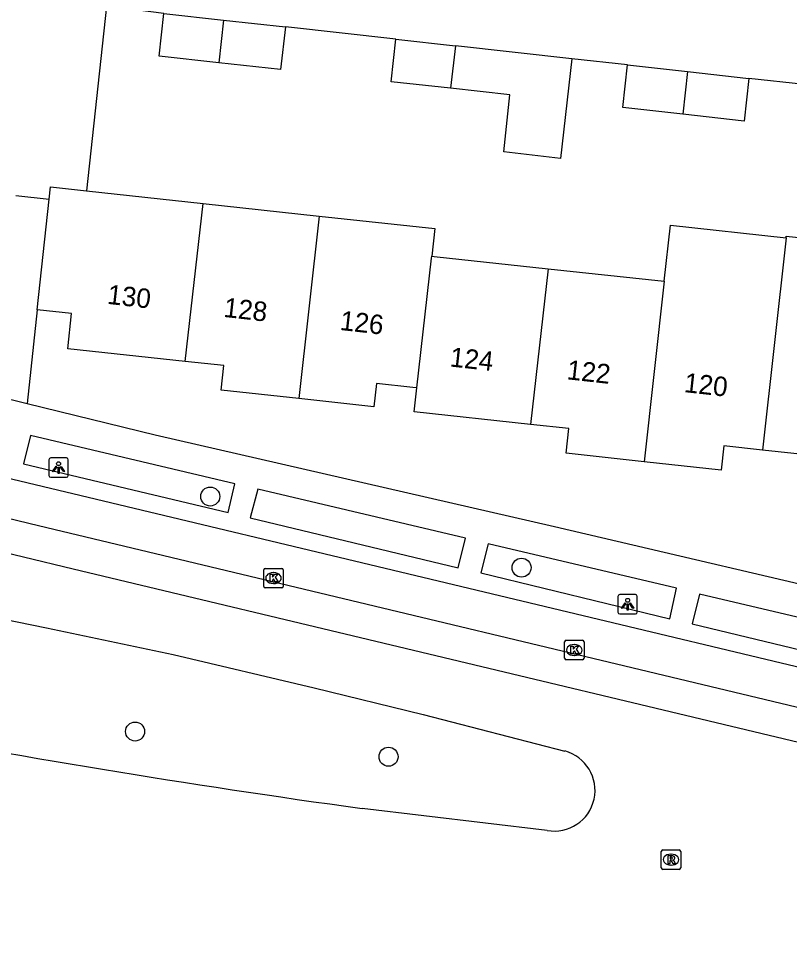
# Model space of a CAD drawing. Extents: x 162026 to 163499, y 387297 to 388169.
# Drawn here: x 162397.42 to 162437.09, y 387380.41 to 387428.11 of the extents above; entities that cross this region are included whole.
import ezdxf

# ---------------------------------------------------------------- set-up
doc = ezdxf.new("R2010")
doc.units = 0
for name, color, linetype in [('IMGEO_Boom', 7, 'Continuous'), ('IMGEO_Kolk', 7, 'Continuous'), ('IMGEO_Lichtpunt', 7, 'Continuous'), ('IMGEO_Pand', 7, 'Continuous'), ('IMGEO_Pand_nummerreeks', 7, 'Continuous'), ('IMGEO_Rijbaan_lokaal_gesloten', 7, 'Continuous'), ('IMGEO_Rijbaan_lokaal_open', 7, 'Continuous'), ('IMGEO_Rioolput', 7, 'Continuous'), ('IMGEO_Voetpad_open', 7, 'Continuous')]:
    doc.layers.add(name, color=color, linetype=linetype)

msp = doc.modelspace()

# ---------------------------------------------------------------- linework, layer by layer
at = {"layer": 'IMGEO_Boom'}
for centre in [(162407.286, 387403.51), (162423.306, 387399.849), (162403.416, 387391.416), (162416.459, 387390.119)]:
    msp.add_circle(centre, 0.489, dxfattribs=at)
at = {"layer": 'IMGEO_Kolk'}
for p, q in [((162410.039, 387398.886), (162410.039, 387399.738)), ((162410.114, 387399.812), (162410.966, 387399.812)), ((162411.04, 387399.738), (162411.04, 387398.886)), ((162410.527, 387399.592), (162410.552, 387399.592)), ((162410.966, 387398.812), (162410.114, 387398.812)), ((162410.55, 387399.032), (162410.525, 387399.032)), ((162425.52, 387395.183), (162425.52, 387396.035)), ((162425.595, 387396.109), (162426.447, 387396.109)), ((162426.008, 387395.889), (162426.033, 387395.889)), ((162426.521, 387396.035), (162426.521, 387395.183)), ((162426.447, 387395.109), (162425.595, 387395.109)), ((162426.031, 387395.329), (162426.006, 387395.329))]:
    msp.add_line(p, q, dxfattribs=at)
for points in [[(162410.039, 387398.886), (162410.039, 387399.738)], [(162410.114, 387399.812), (162410.966, 387399.812)], [(162411.04, 387399.738), (162411.04, 387398.886)], [(162410.36, 387399.512), (162410.483, 387399.512), (162410.483, 387399.361), (162410.613, 387399.512), (162410.777, 387399.512), (162410.631, 387399.361), (162410.784, 387399.112), (162410.632, 387399.112), (162410.547, 387399.276), (162410.483, 387399.209), (162410.483, 387399.112), (162410.36, 387399.112), (162410.36, 387399.512)], [(162410.966, 387398.812), (162410.114, 387398.812)], [(162425.52, 387395.183), (162425.52, 387396.035)], [(162425.595, 387396.109), (162426.447, 387396.109)], [(162426.521, 387396.035), (162426.521, 387395.183)], [(162425.841, 387395.809), (162425.964, 387395.809), (162425.964, 387395.658), (162426.094, 387395.809), (162426.258, 387395.809), (162426.112, 387395.658), (162426.265, 387395.409), (162426.113, 387395.409), (162426.028, 387395.573), (162425.964, 387395.506), (162425.964, 387395.409), (162425.841, 387395.409), (162425.841, 387395.809)], [(162426.447, 387395.109), (162425.595, 387395.109)]]:
    msp.add_lwpolyline(points, dxfattribs=at)
for centre, start, end in [((162410.116, 387399.736), 91.552, 178.448), ((162410.116, 387399.736), 91.552, 178.448), ((162410.964, 387399.736), 1.552, 88.448), ((162410.964, 387399.736), 1.552, 88.448), ((162410.116, 387398.888), 181.552, 268.448), ((162410.116, 387398.888), 181.552, 268.448), ((162410.964, 387398.888), 271.552, 358.448), ((162410.964, 387398.888), 271.552, 358.448), ((162425.597, 387396.033), 91.552, 178.448), ((162425.597, 387396.033), 91.552, 178.448), ((162426.445, 387396.033), 1.552, 88.448), ((162426.445, 387396.033), 1.552, 88.448), ((162425.597, 387395.185), 181.552, 268.448), ((162425.597, 387395.185), 181.552, 268.448), ((162426.445, 387395.185), 271.552, 358.448), ((162426.445, 387395.185), 271.552, 358.448)]:
    msp.add_arc(centre, 0.0765, start, end, dxfattribs=at)
for centre, major_axis, ratio, start_param, end_param in [((162410.526, 387399.312), (-0.387, 0.002), 0.722429, 4.712389, 7.853982), ((162410.551, 387399.312), (-0.39, 0.002), 0.717154, 1.570796, 4.712389), ((162426.007, 387395.609), (-0.387, 0.002), 0.722429, 4.712389, 7.853982), ((162426.032, 387395.609), (-0.39, 0.002), 0.717154, 1.570796, 4.712389)]:
    msp.add_ellipse(centre, major_axis=major_axis, ratio=ratio, start_param=start_param, end_param=end_param, dxfattribs=at)
at = {"layer": 'IMGEO_Lichtpunt'}
for p, q in [((162398.98, 387405.4), (162398.98, 387404.593)), ((162398.98, 387405.4), (162398.98, 387404.593)), ((162399.882, 387405.495), (162399.074, 387405.495)), ((162399.882, 387405.495), (162399.074, 387405.495)), ((162399.976, 387404.593), (162399.976, 387405.4)), ((162399.976, 387404.593), (162399.976, 387405.4)), ((162399.074, 387404.499), (162399.882, 387404.499)), ((162399.074, 387404.499), (162399.882, 387404.499)), ((162428.267, 387398.371), (162428.267, 387397.564)), ((162428.267, 387398.371), (162428.267, 387397.564)), ((162429.169, 387398.466), (162428.361, 387398.466)), ((162429.169, 387398.466), (162428.361, 387398.466)), ((162429.263, 387397.564), (162429.263, 387398.371)), ((162429.263, 387397.564), (162429.263, 387398.371)), ((162428.361, 387397.47), (162429.169, 387397.47)), ((162428.361, 387397.47), (162429.169, 387397.47))]:
    msp.add_line(p, q, dxfattribs=at)
for points in [[(162399.354, 387405.064), (162399.393, 387405.036), (162399.205, 387404.774), (162399.167, 387404.801), (162399.354, 387405.064)], [(162399.456, 387405.016), (162399.503, 387405.016), (162399.503, 387404.694), (162399.456, 387404.694), (162399.456, 387405.016)], [(162399.566, 387405.036), (162399.604, 387405.063), (162399.791, 387404.801), (162399.752, 387404.773), (162399.566, 387405.036)], [(162428.641, 387398.035), (162428.68, 387398.007), (162428.492, 387397.745), (162428.454, 387397.772), (162428.641, 387398.035)], [(162428.743, 387397.987), (162428.79, 387397.987), (162428.79, 387397.665), (162428.743, 387397.665), (162428.743, 387397.987)], [(162428.853, 387398.007), (162428.891, 387398.034), (162429.078, 387397.772), (162429.039, 387397.744), (162428.853, 387398.007)]]:
    msp.add_lwpolyline(points, dxfattribs=at)
for centre in [(162399.479, 387405.198), (162428.766, 387398.169)]:
    msp.add_circle(centre, 0.0994, dxfattribs=at)
for centre, start, end in [((162399.074, 387405.4), 90, 180), ((162399.074, 387405.4), 90, 180), ((162399.882, 387405.4), 0, 90), ((162399.882, 387405.4), 0, 90), ((162399.074, 387404.593), 180, 270), ((162399.074, 387404.593), 180, 270), ((162399.882, 387404.593), 270, 0), ((162399.882, 387404.593), 270, 360), ((162428.361, 387398.371), 90, 180), ((162428.361, 387398.371), 90, 180), ((162429.169, 387398.371), 0, 90), ((162429.169, 387398.371), 0, 90), ((162428.361, 387397.564), 180, 270), ((162428.361, 387397.564), 180, 270), ((162429.169, 387397.564), 270, 0), ((162429.169, 387397.564), 270, 360)]:
    msp.add_arc(centre, 0.0946, start, end, dxfattribs=at)
at = {"layer": 'IMGEO_Pand'}
for points in [[(162407.724, 387425.836), (162404.65, 387426.18), (162404.89, 387428.37)], [(162404.89, 387428.37), (162407.97, 387428.03)], [(162407.97, 387428.03), (162407.724, 387425.836)], [(162407.97, 387428.03), (162411.15, 387427.68)], [(162411.15, 387427.68), (162410.9, 387425.48), (162407.724, 387425.836)], [(162419.657, 387424.518), (162416.6, 387424.86), (162416.84, 387427.05)], [(162416.84, 387427.05), (162419.904, 387426.712)], [(162419.904, 387426.712), (162419.657, 387424.518)], [(162425.89, 387426.044), (162419.904, 387426.712)], [(162425.89, 387426.044), (162425.318, 387420.914), (162422.396, 387421.242), (162422.709, 387424.176), (162419.657, 387424.518)], [(162431.598, 387423.184), (162428.51, 387423.53), (162428.75, 387425.72)], [(162428.75, 387425.72), (162431.842, 387425.379)], [(162431.842, 387425.379), (162431.598, 387423.184)], [(162435.01, 387425.03), (162434.76, 387422.83), (162431.598, 387423.184)], [(162431.842, 387425.379), (162435.01, 387425.03)], [(162398.996, 387418.812), (162399.064, 387419.442), (162400.911, 387419.241)], [(162400.911, 387419.241), (162406.912, 387418.59)], [(162398.38, 387413.12), (162398.996, 387418.812)], [(162406.001, 387410.462), (162406.912, 387418.59)], [(162406.912, 387418.59), (162412.884, 387417.942)], [(162412.884, 387417.942), (162411.84, 387408.552)], [(162412.884, 387417.942), (162418.844, 387417.296), (162418.685, 387415.884)], [(162430.645, 387414.587), (162430.965, 387417.474), (162436.918, 387416.828)], [(162436.918, 387416.828), (162436.927, 387416.912), (162442.872, 387416.267), (162442.549, 387413.295), (162441.676, 387405.253), (162435.704, 387405.901)], [(162436.918, 387416.828), (162435.704, 387405.901)], [(162417.922, 387409.102), (162418.674, 387415.784), (162418.685, 387415.884)], [(162418.685, 387415.884), (162418.808, 387415.871), (162424.683, 387415.234)], [(162424.683, 387415.234), (162423.767, 387407.219)], [(162424.683, 387415.234), (162430.645, 387414.587)], [(162430.645, 387414.587), (162429.615, 387405.3)], [(162406.001, 387410.462), (162399.952, 387411.118), (162400.149, 387412.928), (162398.38, 387413.12)], [(162411.84, 387408.552), (162407.851, 387408.985), (162407.988, 387410.246), (162406.001, 387410.462)], [(162417.922, 387409.102), (162417.71, 387409.125), (162415.833, 387409.328), (162415.703, 387408.133), (162411.84, 387408.552)], [(162423.767, 387407.219), (162417.783, 387407.869), (162417.922, 387409.102)], [(162429.615, 387405.3), (162425.601, 387405.735), (162425.739, 387407.005), (162423.767, 387407.219)], [(162435.704, 387405.901), (162433.715, 387406.117), (162433.58, 387404.87), (162429.615, 387405.3)]]:
    msp.add_lwpolyline(points, dxfattribs=at)
at = {"layer": 'IMGEO_Rijbaan_lokaal_gesloten'}
for points in [[(162481.027, 387380.405), (162452.771, 387387.216), (162400.227, 387399.776), (162389.995, 387402.241), (162380.574, 387405.433)], [(162443.887, 387391.121), (162398.449, 387402.001), (162390.78, 387403.852), (162390.534, 387403.927)]]:
    msp.add_lwpolyline(points, dxfattribs=at)
at = {"layer": 'IMGEO_Rijbaan_lokaal_open'}
for points in [[(162404.89, 387428.37), (162401.939, 387428.743), (162400.911, 387419.241)], [(162416.84, 387427.05), (162411.15, 387427.68)], [(162428.75, 387425.72), (162425.89, 387426.044)], [(162437.861, 387424.709), (162435.01, 387425.03)], [(162397.281, 387418.997), (162398.996, 387418.812)], [(162376.494, 387401.259), (162376.793, 387401.271), (162398.853, 387396.753), (162405.374, 387395.373), (162412.634, 387393.669), (162418.248, 387392.291), (162425.53, 387390.413)], [(162424.617, 387386.324), (162415.106, 387387.454)]]:
    msp.add_lwpolyline(points, dxfattribs=at)
for centre, radius, start, end in [((162482.945, 387881.492), 498.674, 259.07678, 262.18127), ((162424.991, 387388.387), 2.097, 259.7128, 75.1139)]:
    msp.add_arc(centre, radius, start, end, dxfattribs=at)
at = {"layer": 'IMGEO_Rioolput'}
for p, q in [((162430.494, 387384.396), (162430.494, 387385.248)), ((162430.569, 387385.322), (162431.421, 387385.322)), ((162430.982, 387385.102), (162431.007, 387385.102)), ((162431.495, 387385.248), (162431.495, 387384.396)), ((162431.005, 387384.542), (162430.98, 387384.542)), ((162431.421, 387384.322), (162430.569, 387384.322))]:
    msp.add_line(p, q, dxfattribs=at)
for points in [[(162430.494, 387384.396), (162430.494, 387385.248)], [(162430.569, 387385.322), (162431.421, 387385.322)], [(162431.083, 387385.02), (162430.831, 387385.022), (162430.831, 387384.622)], [(162431.009, 387384.941), (162430.955, 387384.941), (162430.955, 387384.86)], [(162431.495, 387385.248), (162431.495, 387384.396)], [(162430.831, 387384.622), (162430.955, 387384.622), (162430.955, 387384.784), (162430.966, 387384.784)], [(162430.955, 387384.86), (162431.007, 387384.86)], [(162431.013, 387384.755), (162431.084, 387384.622), (162431.224, 387384.622), (162431.159, 387384.748)], [(162431.421, 387384.322), (162430.569, 387384.322)]]:
    msp.add_lwpolyline(points, dxfattribs=at)
for centre, radius, start, end in [((162430.571, 387385.246), 0.0765, 91.552, 178.448), ((162430.571, 387385.246), 0.0765, 91.552, 178.448), ((162431.015, 387384.845), 0.0964, 77.0061, 93.1865), ((162431.029, 387384.902), 0.0378, 276.6634, 79.6772), ((162431.082, 387384.91), 0.109, 350.3612, 89.416), ((162431.08, 387384.91), 0.112, 277.5842, 350.9817), ((162431.419, 387385.246), 0.0765, 1.552, 88.448), ((162431.419, 387385.246), 0.0765, 1.552, 88.448), ((162430.571, 387384.398), 0.0765, 181.552, 268.448), ((162430.571, 387384.398), 0.0765, 181.552, 268.448), ((162430.965, 387384.731), 0.0533, 26.0293, 88.6989), ((162430.991, 387385.049), 0.19, 274.7715, 282.9687), ((162431.064, 387384.695), 0.108, 29.5134, 73.7905), ((162431.419, 387384.398), 0.0765, 271.552, 358.448), ((162431.419, 387384.398), 0.0765, 271.552, 358.448)]:
    msp.add_arc(centre, radius, start, end, dxfattribs=at)
for centre, major_axis, ratio, start_param, end_param in [((162430.981, 387384.822), (-0.387, 0.002), 0.722429, 4.712389, 7.853982), ((162431.006, 387384.822), (-0.39, 0.002), 0.717154, 1.570796, 4.712389)]:
    msp.add_ellipse(centre, major_axis=major_axis, ratio=ratio, start_param=start_param, end_param=end_param, dxfattribs=at)
at = {"layer": 'IMGEO_Voetpad_open'}
for points in [[(162398.38, 387413.12), (162397.856, 387408.293)], [(162396.253, 387408.686), (162397.856, 387408.293)], [(162397.856, 387408.293), (162404.454, 387406.677), (162424.994, 387401.97), (162442.45, 387397.88)], [(162398.035, 387406.657), (162397.682, 387405.194), (162408.2, 387402.685), (162408.554, 387404.163), (162398.035, 387406.657)], [(162443.695, 387393.247), (162397.49, 387404.3), (162391.744, 387405.681)], [(162409.73, 387403.895), (162409.347, 387402.412), (162420.036, 387399.843), (162420.417, 387401.368), (162409.73, 387403.895)], [(162421.591, 387401.072), (162421.21, 387399.574), (162430.935, 387397.221), (162431.286, 387398.789), (162421.591, 387401.072)], [(162432.469, 387398.487), (162432.092, 387396.966), (162444.703, 387393.926), (162445.078, 387395.51), (162432.469, 387398.487)]]:
    msp.add_lwpolyline(points, dxfattribs=at)

# ---------------------------------------------------------------- texts
at = {"layer": 'IMGEO_Pand_nummerreeks'}
for s, rotation, p in [('130', 353.6001, (162401.952, 387413.43)), ('128', 353.5992, (162407.942, 387412.758)), ('126', 353.6001, (162413.928, 387412.086)), ('124', 353.7548, (162419.583, 387410.206)), ('122', 353.7532, (162425.606, 387409.547)), ('120', 353.7548, (162431.637, 387408.887))]:
    msp.add_text(s, height=1, rotation=rotation, dxfattribs=at).set_placement(p)

doc.saveas('drawing.dxf')
